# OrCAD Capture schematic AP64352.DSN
size D; title: 3.8V TO 40V INPUT, 3.5A LOW IQ SYNCHRONOUS BUCK; rev: 1.0; note: DS41978 Rev. 5 - 2
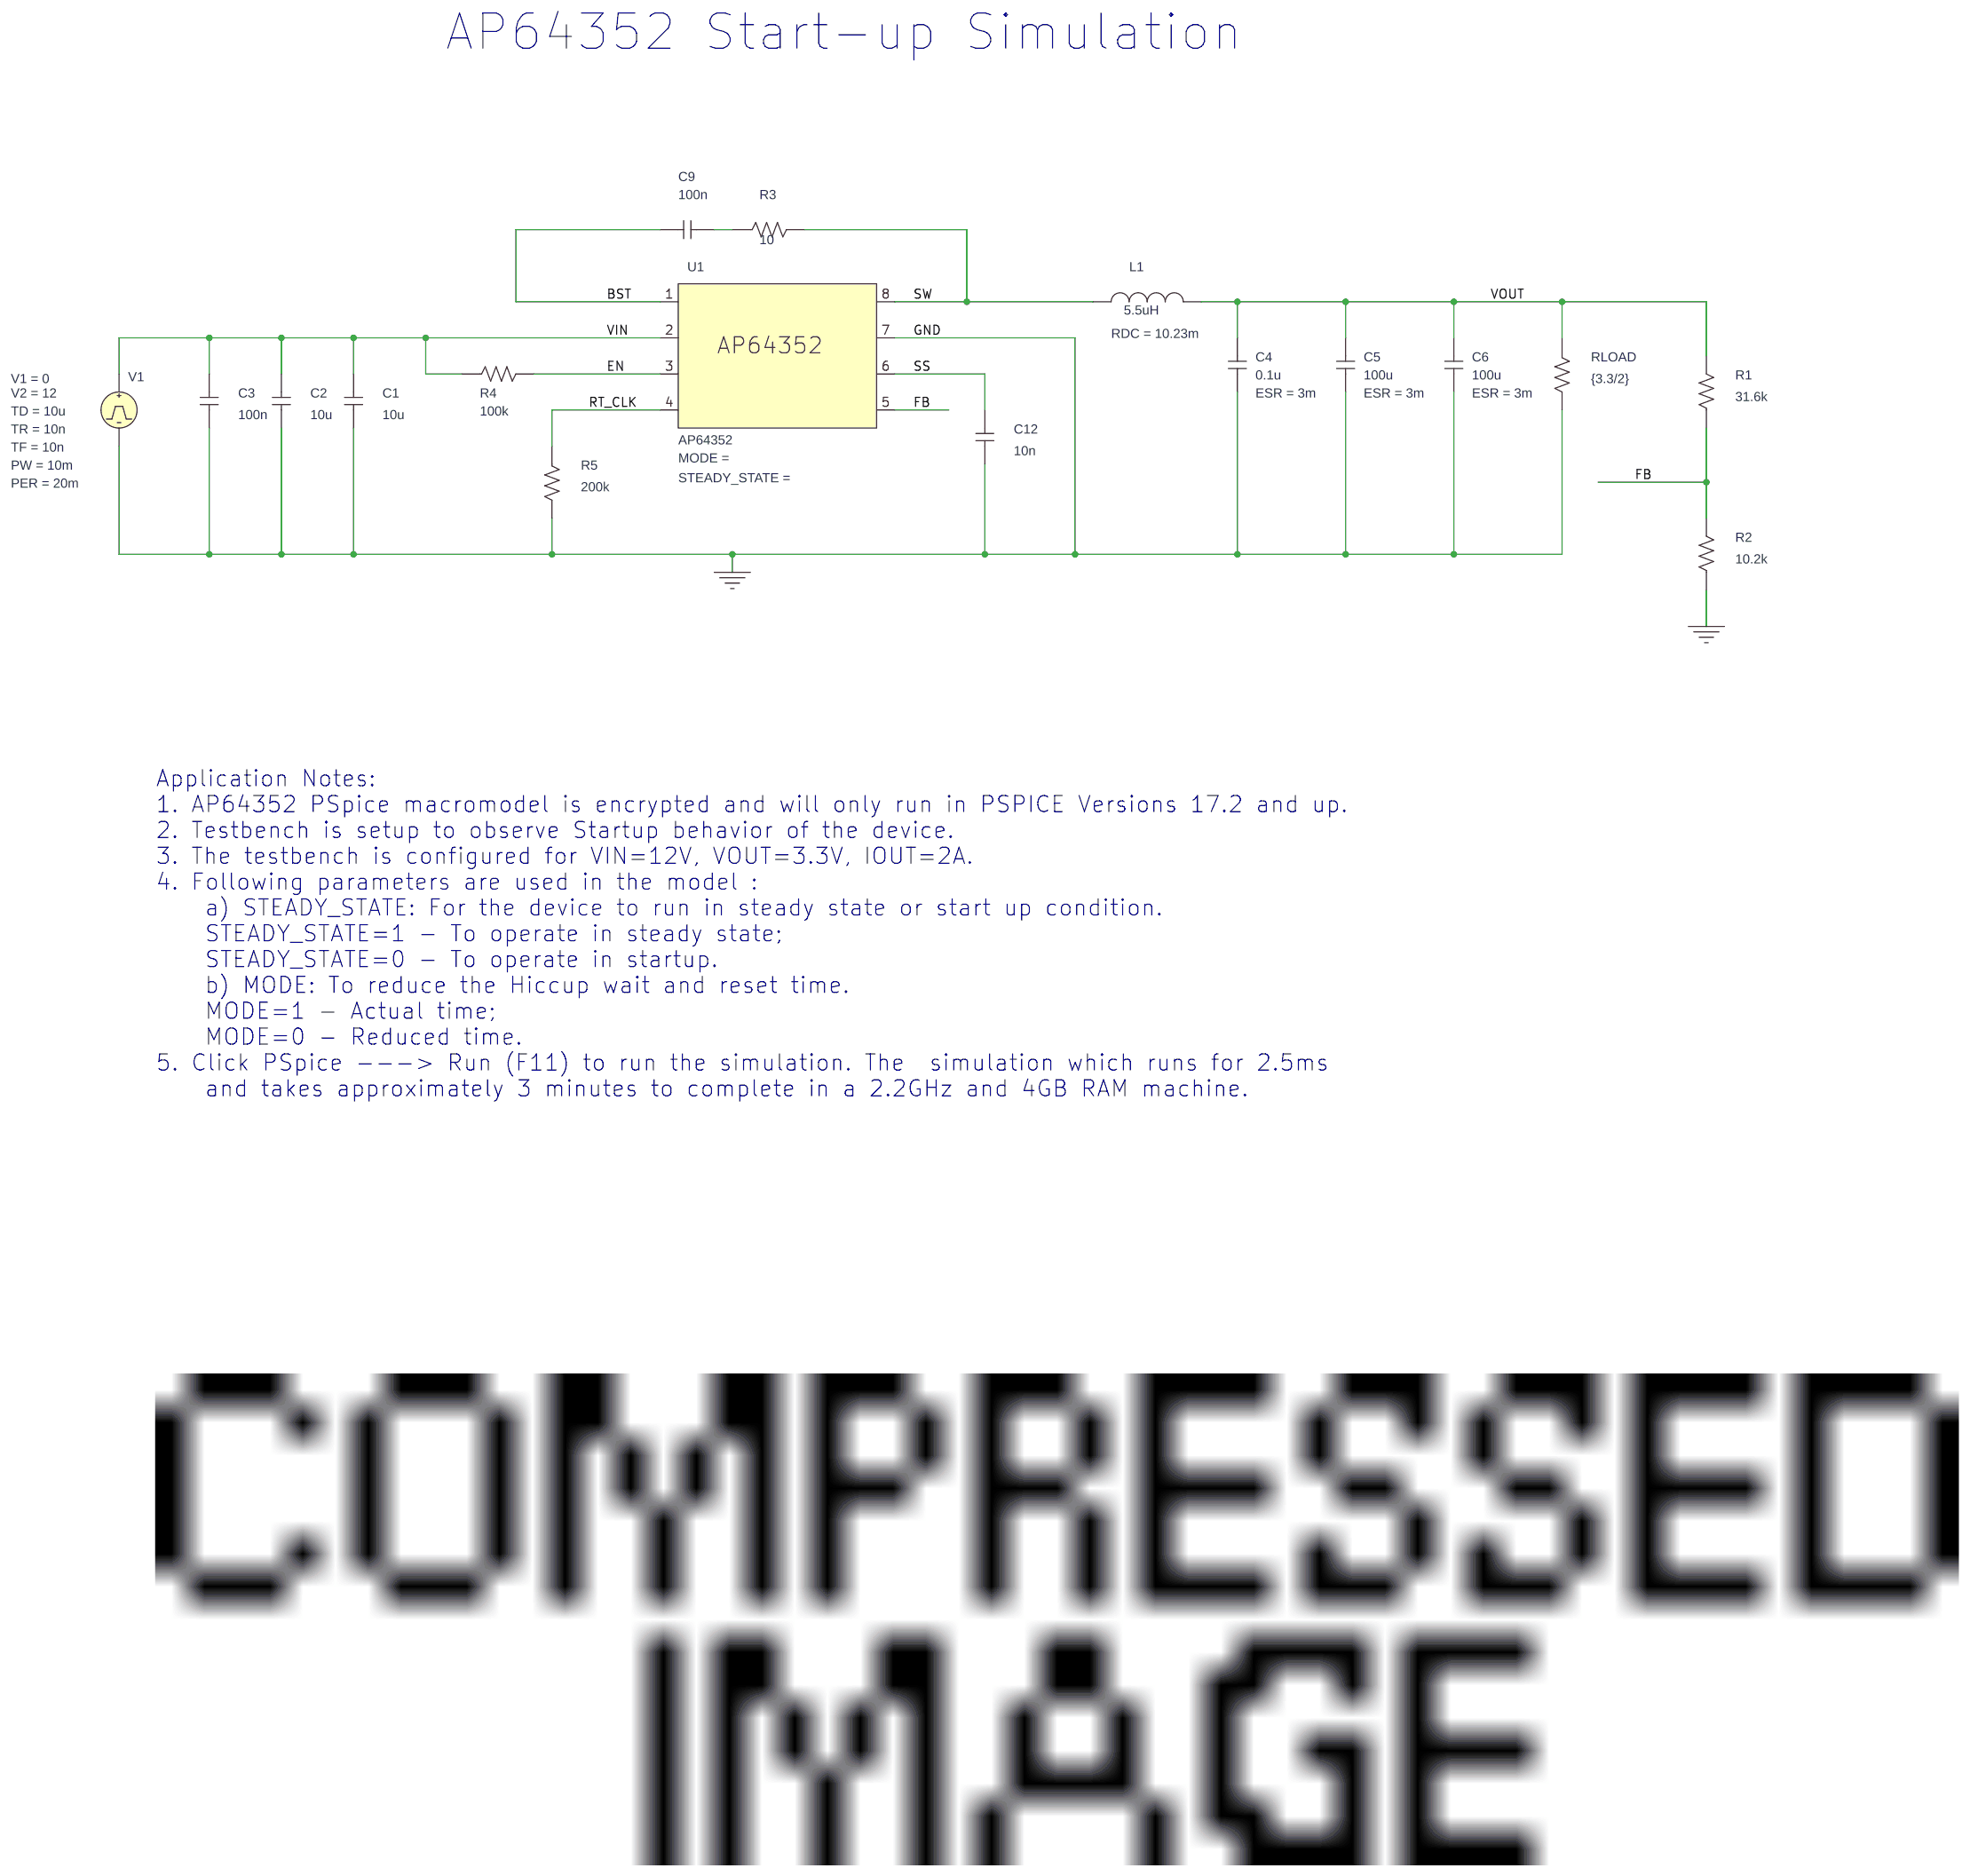
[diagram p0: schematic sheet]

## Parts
C1  10u  [cap196]
C2  10u  [cap196]
C3  100n  [cap196]
C4  0.1u  [RAD/CK05]
C5  100u  [RAD/CK05]
C6  100u  [RAD/CK05]
C9  100n  [cap196]
C12  10n  [cap196]
L1  5.5uH  [DISC/.350x.175/LS.200x.100/.034]
R1  31.6k  [AXRC05]
R2  10.2k  [AXRC05]
R3  10  [AXRC05]
R4  100k  [AXRC05]
R5  200k  [AXRC05]
RLOAD  {3.3/2}  [AXRC05]
U1  AP64352
V1  VPULSE

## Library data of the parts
C1-C3 C9 C12 = C
C4-C6 = C: AppProp: InductiveSlave:;SRF:;PrevCap:220;PrevESL:; ESR: 3m
L1 = L: AppProp: SRF:; RDC: 10.23m
R1-R5 RLOAD = R
U1 = AP64352
V1 = VPULSE: PER: 20m; PW: 10m; TD: 10u; TF: 10n; TR: 10n; V1: 0; V2: 12

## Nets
VIN: C1.1 C2.1 C3.1 R4.1 U1.2(VIN) V1.1(+)
0: C1.2 C2.2 C3.2 C4.2 C5.2 C6.2 C12.2 R2.1 R5.2 RLOAD.2 U1.7(GND) V1.2(-)
BST: C9.1 U1.1(BST)
EN: R4.2 U1.3(EN)
FB: R1.1 R2.2 U1.5(FB)
RT_CLK: R5.1 U1.4(RT_CLK)
SS: C12.1 U1.6(SS)
SW: L1.1 R3.2 U1.8(SW)
VOUT: C4.1 C5.1 C6.1 L1.2 R1.2 RLOAD.1
N16073027: C9.2 R3.1

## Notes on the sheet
- AP64352 Start-up Simulation
- Application Notes:
  1. AP64352 PSpice macromodel is encrypted and will only run in PSPICE Versions 17.2 and up.
  2. Testbench is setup to observe Startup behavior of the device.
  3. The testbench is configured for VIN=12V, VOUT=3.3V, IOUT=2A.
  4. Following parameters are used in the model :
      a) STEADY_STATE: For the device to run in steady state or start up condition.
      STEADY_STATE=1 - To operate in steady state;
      STEADY_STATE=0 - To operate in startup.
      b) MODE: To reduce the Hiccup wait and reset time.
      MODE=1 - Actual time;
      MODE=0 - Reduced time.
  5. Click PSpice ---> Run (F11) to run the simulation. The  simulation which runs for 2.5ms
      and takes approximately 3 minutes to complete in a 2.2GHz and 4GB RAM machine.
